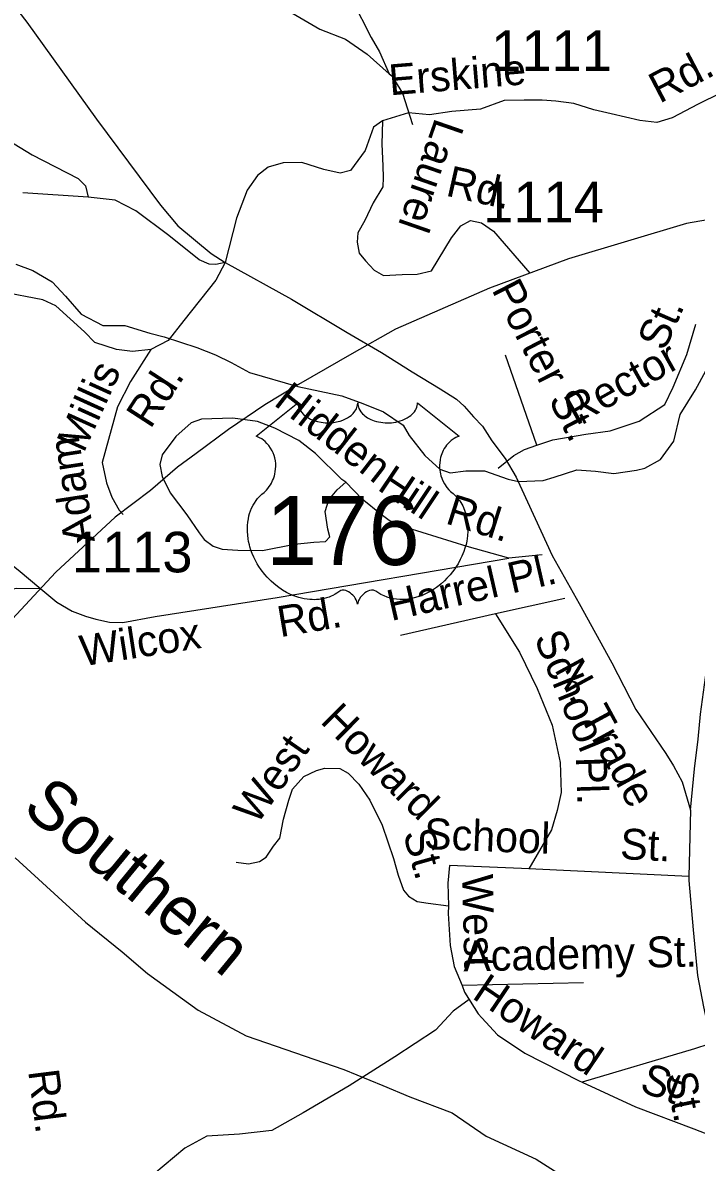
# Model space of a CAD drawing. Extents: x 990631 to 1056237, y 535999 to 585651.
# Drawn here: x 1029934 to 1032009, y 547537 to 551047 of the extents above; entities that cross this region are included whole.
import ezdxf

# ---------------------------------------------------------------- set-up
doc = ezdxf.new("R2010")
doc.units = 0
for name, color, linetype in [('Exist Boundary Political City Limit New', 7, 'Continuous'), ('Exist Hydrographic Creek Single Shore', 7, 'Continuous'), ('Exist Railroad Mainline', 7, 'Continuous'), ('Exist Railroad Mainline Label', 7, 'Continuous'), ('Exist Road Non-System Type 51', 7, 'Continuous'), ('Exist Road Non-System Type 51 Label', 7, 'Continuous'), ('Exist Road Primary NC Attributed', 7, 'Continuous'), ('Exist Road Primary US Attributed', 7, 'Continuous'), ('Exist Road Primary US Label', 7, 'Continuous'), ('Exist Road Primary US Shield CELL', 7, 'Continuous'), ('Exist Road Primary US Shield Number Label', 7, 'Continuous'), ('Exist Road Secondary Type 41 Attributed', 7, 'Continuous'), ('Exist Road Secondary Type 51 Attributed', 7, 'Continuous'), ('Exist Road Secondary Type 51 Label', 7, 'Continuous'), ('Exist Road Secondary Type 51 Number Label', 7, 'Continuous')]:
    doc.layers.add(name, color=color, linetype=linetype)

msp = doc.modelspace()

# ---------------------------------------------------------------- linework, layer by layer
at = {"layer": 'Exist Boundary Political City Limit New'}
msp.add_lwpolyline([(1032315.2, 550487.8), (1031979.1, 550428.5), (1031615.4, 550320.1), (1031372.3, 550229.8), (1031082.1, 550103), (1030947.7, 550027.3), (1030783.1, 549933), (1030679.9, 549869.8), (1030567.6, 549794.2), (1030468.1, 549720.6), (1030410.1, 549678.4), (1030326.8, 549606.4), (1030218.9, 549524.4), (1030035.4, 549354.2), (1029900.6, 549210.2)], dxfattribs=at)
at = {"layer": 'Exist Hydrographic Creek Single Shore'}
msp.add_lwpolyline([(1029912.2, 550304), (1029964.4, 550284.3), (1030024.7, 550248.8), (1030065, 550205.1), (1030113.4, 550149.4), (1030180.7, 550114.6), (1030248.1, 550114.6), (1030325.2, 550091.5), (1030369.5, 550079.9), (1030469.7, 550047.1), (1030527.4, 550024), (1030575.6, 550000.9), (1030632.8, 549969.5), (1030781.1, 549926.7), (1030917.4, 549897.8), (1030981.6, 549874.3), (1031045.8, 549848.8), (1031106, 549807.2), (1031124.3, 549775.3), (1031172.8, 549713.7), (1031219.1, 549672), (1031251.1, 549660.3), (1031299.1, 549666.6), (1031357.1, 549667.1), (1031429.3, 549641.7), (1031461.4, 549633.9), (1031537.4, 549636.6), (1031571.3, 549646.9), (1031641.1, 549669.5), (1031699.1, 549665.9), (1031755.1, 549658.4), (1031825.1, 549669), (1031851, 549675.2), (1031898.9, 549701.7), (1031940.4, 549758.1), (1031959.8, 549840.4), (1032007.2, 549916.9), (1032038.8, 549975.2)], dxfattribs=at)
at = {"layer": 'Exist Railroad Mainline'}
msp.add_lwpolyline([(1029909.8, 548474.7), (1030127.3, 548276.1), (1030240.3, 548184.7), (1030318.2, 548118.3), (1030473.9, 548005.6), (1030622, 547926.3), (1030922.7, 547822.4), (1031043.7, 547773.1), (1031126.6, 547738.4), (1031257.1, 547688.6), (1031361.6, 547617.5), (1031516.3, 547546.4), (1031606.1, 547489)], dxfattribs=at)
at = {"layer": 'Exist Road Non-System Type 51'}
for p, q in [((1031534.2, 549408.1), (1031431.7, 549397.3)), ((1031603.9, 549273.8), (1031390.3, 549226.7)), ((1031390.3, 549226.7), (1031097.8, 549159.9)), ((1031986.6, 548417), (1031493.1, 548440.7)), ((1031661.9, 548089.2), (1031287.4, 548081.1))]:
    msp.add_line(p, q, dxfattribs=at)
for points in [[(1030250.8, 551514.7), (1030343.7, 551477.6), (1030413.1, 551459.4), (1030458.6, 551444.1), (1030478.1, 551427.3), (1030518.2, 551364), (1030560.1, 551296.6), (1030611.7, 551224.9), (1030667.4, 551151.1), (1030737.7, 551092.7), (1030849.6, 551027.2), (1030928.6, 550996.6), (1030995.3, 550950.5), (1031063.3, 550890.3)], [(1030868.5, 551370.8), (1030876.1, 551292.6), (1030886.6, 551248.2), (1030914.4, 551175.2), (1030948.6, 551118.1), (1031006.9, 551002.1), (1031033.4, 550957.3), (1031063.3, 550890.3)], [(1029392.8, 550911.5), (1029486.1, 550886.4), (1029576.9, 550844.5), (1029699.3, 550793.9), (1029850.3, 550708.5), (1029962.7, 550640.8), (1030104.1, 550567.1), (1030127, 550545.3), (1030135.5, 550510.3)], [(1031063.3, 550890.3), (1031071.2, 550883.9), (1031103.5, 550830.8), (1031134.4, 550733.8)], [(1031517.8, 549745.7), (1031566.9, 549762.8), (1031669.2, 549779.8), (1031743.9, 549790.5), (1031833.5, 549820.4), (1031912.4, 549871.6), (1031938, 549924.9), (1031980.6, 550025.2), (1032008.3, 550119.1)], [(1031517.8, 549745.7), (1031421.8, 550023.1)], [(1030928.9, 549631.7), (1030917.1, 549640.2), (1030835.7, 549720.8), (1030784.8, 549760.5), (1030710.2, 549798.8), (1030656.8, 549818.5), (1030580.9, 549829), (1030484.9, 549826.1), (1030452.4, 549815), (1030405.1, 549772.5), (1030363.2, 549715.9), (1030356.2, 549686.1), (1030363.1, 549649.7), (1030387.4, 549599), (1030439.3, 549531.3), (1030477.6, 549476.2), (1030493, 549455.4), (1030520.2, 549434.7), (1030548, 549425.7), (1030596, 549422.2), (1030672, 549421.8), (1030770.6, 549440.6), (1030830.9, 549446.6), (1030867, 549449.5), (1030879.5, 549463.1), (1030874.2, 549487.4), (1030865.8, 549541.6), (1030877.2, 549577.3), (1030902.2, 549608.5), (1030928.9, 549631.7)], [(1031398.5, 549675), (1031447.4, 549713.7), (1031479.4, 549732.9), (1031517.8, 549745.7)], [(1031431.7, 549397.3), (1031302.8, 549433.5), (1031118.5, 549491.5), (1031063.1, 549513.4), (1031037.7, 549532.1), (1030979.3, 549580.1), (1030928.9, 549631.7)], [(1029800.8, 549467.8), (1029816.1, 549443.3), (1029919.5, 549361.9), (1029989.8, 549303.5)], [(1029989.8, 549303.5), (1030038.5, 549261.9), (1030085.6, 549234.4), (1030127.1, 549219.1), (1030158.9, 549210.1), (1030200.6, 549200.6), (1030242.5, 549199.4), (1030341.2, 549218.2), (1030717.3, 549276.3), (1031431.7, 549397.3)], [(1029989.8, 549303.5), (1029913.7, 549304), (1029869.3, 549293.3), (1029828.8, 549276.7), (1029800.1, 549253.5), (1029775.1, 549224.4), (1029767.5, 549174.5), (1029755, 549099)], [(1031390.3, 549226.7), (1031464.5, 549108.1), (1031518.9, 548996.4), (1031565.2, 548882.8), (1031589.7, 548767.9), (1031592.7, 548675.8), (1031580.9, 548620), (1031562.9, 548560.6), (1031493.1, 548440.7)], [(1030591.2, 548461.7), (1030628.9, 548456.5), (1030663.3, 548463.4), (1030683.7, 548476.8), (1030706.8, 548510), (1030725.5, 548535.4), (1030737.5, 548593.2), (1030753.3, 548652.7), (1030764.4, 548686.3), (1030799.8, 548725.2), (1030838.4, 548744), (1030864.5, 548751.1), (1030910.5, 548749.8), (1030936, 548734.9), (1030969.2, 548701.8), (1031003.6, 548652.7), (1031041, 548575.3), (1031075.8, 548472.1), (1031090.2, 548421.6), (1031106.6, 548375.1), (1031122.1, 548356.6), (1031149.5, 548339.8), (1031183.4, 548334.7), (1031245.3, 548326.7)], [(1031493.1, 548440.7), (1031471.1, 548441.6), (1031249.2, 548450.6), (1031243.5, 548396.7), (1031245.3, 548326.7)], [(1031245.3, 548326.7), (1031244.4, 548302.7), (1031251.2, 548204.3), (1031263.1, 548140), (1031287.4, 548081.1)], [(1031287.4, 548081.1), (1031294.8, 548061), (1031336.6, 547993.5), (1031348.2, 547981.1)], [(1031309.5, 548038.3), (1031260.4, 548001.9), (1031205.1, 547943.5), (1031080.4, 547861.3), (1030939.4, 547772.2), (1030797.3, 547688.6), (1030701.1, 547634.2), (1030601.4, 547623.1), (1030500.5, 547617.5), (1030433.6, 547579.8), (1030337.5, 547500.4), (1030270.6, 547429.3), (1030230.6, 547371.3), (1030232, 547313.4), (1030235.4, 547293.3), (1030257, 547277.6), (1030290.7, 547268.5), (1030430.6, 547262.1)], [(1031348.2, 547981.1), (1031396.6, 547929.5), (1031480.8, 547872.8), (1031648.2, 547787.4), (1031658.1, 547783)], [(1032048, 547900.6), (1032003.7, 547886), (1031658.1, 547783)], [(1031658.1, 547783), (1031821.8, 547707.8), (1032001.7, 547640), (1032102.6, 547600.8)]]:
    msp.add_lwpolyline(points, dxfattribs=at)
at = {"layer": 'Exist Road Primary NC Attributed'}
msp.add_lwpolyline([(1031991.1, 548621), (1032003.3, 548748.6), (1032014.7, 548840), (1032022.6, 548916.7), (1032040.3, 549052.3), (1032067.8, 549166.3), (1032085.5, 549243), (1032107.1, 549315.7), (1032130.6, 549476.9), (1032099.2, 549712.8), (1032118.9, 549791.4), (1032152.2, 549895.6), (1032173.9, 549982), (1032177.8, 550080.3), (1032177.8, 550186.5), (1032197.4, 550247.4), (1032348.7, 550424.3), (1032370.2, 550499.1)], dxfattribs=at)
at = {"layer": 'Exist Road Primary US Attributed'}
for points in [[(1028663.1, 551794), (1028748.1, 551769.7), (1028821.5, 551746.1), (1028864.3, 551725.4), (1028921.1, 551689.7), (1028948.3, 551666.7), (1028972.5, 551645.6), (1029182.8, 551417.8), (1029236.5, 551379.7), (1029268.5, 551363.9), (1029300.5, 551351.9), (1029393, 551323.8), (1029503.5, 551296.6), (1029677.5, 551264.2), (1029741.6, 551243.4), (1029777.2, 551225.2), (1029810.4, 551201.7), (1029865, 551154.9), (1029945.8, 551049.7), (1030160.9, 550750.5), (1030358, 550485.6), (1030412, 550421.9), (1030514.5, 550336), (1030557.1, 550309.2)], [(1030557.1, 550309.2), (1030762.1, 550195.3), (1030932.9, 550093.2), (1031039, 550031.5), (1031134, 549971.8), (1031219.9, 549919.3), (1031270.4, 549887.9), (1031293.6, 549865.7), (1031322.9, 549833.3), (1031350.2, 549805), (1031379.5, 549759.5), (1031419.9, 549704.9), (1031454.3, 549647.3), (1031565.4, 549405.6), (1031648.3, 549258), (1031749.4, 549075), (1031823.1, 548931.4), (1031915.1, 548795.9), (1031939.3, 548757.5), (1031965.6, 548709), (1031991.1, 548621)], [(1031991.1, 548621), (1031986.6, 548417), (1031986.1, 548405), (1031999.3, 548252.5), (1032012.8, 548111.9), (1032031.3, 548015.4), (1032054.5, 547911.3), (1032078.8, 547819.2), (1032103, 547685.8), (1032131.3, 547551.3), (1032182.8, 547297.5), (1032199, 547219.7), (1032210.1, 547179.2), (1032231.3, 547137.8), (1032259.6, 547102.4), (1032311.2, 547066), (1032444.6, 546970.9), (1032553.7, 546906.2), (1032630.5, 546861.7), (1032739.1, 546782.3), (1032803.9, 546737.7), (1032850.5, 546702.3), (1032897.1, 546653.6)]]:
    msp.add_lwpolyline(points, dxfattribs=at)
at = {"layer": 'Exist Road Primary US Shield CELL'}
msp.add_lwpolyline([(1030781.8, 549876.1), (1030782.1, 549870.8), (1030783.4, 549864.5), (1030784.4, 549861.2), (1030787.3, 549855), (1030792.2, 549847.6), (1030799, 549840.4), (1030806.7, 549834.1), (1030811.8, 549830.7), (1030820.6, 549826), (1030830.5, 549821.8), (1030841.6, 549818.6), (1030852.9, 549816.4), (1030865.3, 549815), (1030877.6, 549814.8), (1030890.8, 549815.7), (1030905.3, 549818.6), (1030912.1, 549820.3), (1030919.6, 549822.9), (1030926.6, 549825.8), (1030934.3, 549829.9), (1030940.4, 549833.8), (1030945.3, 549837.3), (1030952.1, 549843.9), (1030957.5, 549850.6), (1030959.8, 549854.4), (1030961.8, 549858.1), (1030964.5, 549865.8), (1030965.2, 549869.2), (1030965.8, 549876.4), (1030966.2, 549870.4), (1030966.8, 549866.7), (1030967.8, 549863), (1030969.3, 549859.1), (1030972.1, 549853.7), (1030975.1, 549849.1), (1030980.8, 549842.3), (1030984.4, 549839), (1030987.7, 549836.3), (1030996.4, 549830.3), (1031006.6, 549825.2), (1031011.6, 549823), (1031016.8, 549821.1), (1031023.3, 549819.2), (1031030.1, 549817.6), (1031036.8, 549816.4), (1031043.6, 549815.4), (1031050.6, 549814.9), (1031056.3, 549814.8), (1031063.3, 549814.8), (1031069.7, 549815.2), (1031076.3, 549816), (1031083.6, 549817.2), (1031089.5, 549818.5), (1031097.2, 549820.5), (1031104.2, 549823), (1031110.4, 549825.7), (1031118.3, 549829.9), (1031124.8, 549833.9), (1031129.5, 549837.7), (1031135.1, 549842.9), (1031140.4, 549849), (1031143.6, 549853.5), (1031145.8, 549858.1), (1031147.8, 549863), (1031149.1, 549868.2), (1031149.7, 549872.7), (1031149.8, 549876.5), (1031278.4, 549774), (1031275.4, 549772.9), (1031268.4, 549769.5), (1031262.8, 549766.2), (1031254, 549760), (1031250.2, 549756.5), (1031246.4, 549753), (1031242.9, 549749.2), (1031239.8, 549745.6), (1031236.1, 549740.4), (1031232.8, 549735.3), (1031229.5, 549729.6), (1031227.1, 549724.6), (1031223.2, 549714.3), (1031221.3, 549707.8), (1031220, 549702.2), (1031218.5, 549690.7), (1031218.1, 549685.3), (1031218.1, 549679.9), (1031218.4, 549674.2), (1031219, 549668.7), (1031220, 549663), (1031220.9, 549658), (1031222.5, 549651.8), (1031224.7, 549644.7), (1031227.6, 549637.8), (1031233.4, 549626.6), (1031241, 549615.2), (1031246.4, 549608.8), (1031251.7, 549603.4), (1031259.6, 549596.7), (1031263.9, 549592.9), (1031268.9, 549587.9), (1031276.9, 549578.6), (1031280.2, 549574.2), (1031283.5, 549569.2), (1031286.5, 549564.2), (1031289.6, 549558.7), (1031292, 549553.9), (1031296.5, 549542.9), (1031299.8, 549532.2), (1031301.3, 549526.5), (1031303.7, 549513.9), (1031304.6, 549507.7), (1031305.6, 549495.4), (1031305.7, 549480.5), (1031304.5, 549466.4), (1031301.9, 549449.9), (1031299.7, 549440), (1031296.3, 549428.5), (1031293, 549418.6), (1031287.1, 549403.9), (1031281.9, 549393.3), (1031275.2, 549380.8), (1031270.5, 549373.3), (1031265.1, 549365.2), (1031258.4, 549355.9), (1031250.5, 549346.1), (1031241, 549335.7), (1031233.3, 549328), (1031223.3, 549319), (1031217.2, 549314), (1031208.6, 549307.5), (1031196.7, 549299.6), (1031185, 549292.8), (1031175.1, 549287.7), (1031166.3, 549283.9), (1031154.9, 549279.6), (1031135.9, 549274.3), (1031129, 549272.9), (1031120.8, 549271.7), (1031113.1, 549270.9), (1031105.7, 549270.5), (1031095.6, 549270.5), (1031085.7, 549271.2), (1031076.3, 549272.6), (1031066.5, 549274.6), (1031056.2, 549277.7), (1031046.9, 549281.3), (1031037.5, 549286), (1031021.6, 549296), (1031017, 549298.4), (1031014.4, 549299.1), (1031008.3, 549299.4), (1031002.5, 549298.2), (1030996.6, 549295.8), (1030993, 549293.9), (1030988.2, 549290.8), (1030984.6, 549287.9), (1030980.2, 549283.8), (1030977.2, 549280.3), (1030974.8, 549277.5), (1030970.4, 549270.5), (1030968.8, 549267.1), (1030967.1, 549262.8), (1030965.6, 549256.4), (1030963.6, 549264.5), (1030961.2, 549269.8), (1030958.5, 549274.3), (1030955.7, 549278.4), (1030951.2, 549283.5), (1030947.2, 549287.4), (1030942.3, 549291.4), (1030937.1, 549294.5), (1030933, 549296.6), (1030929.2, 549298), (1030924.6, 549299.2), (1030920.8, 549299.5), (1030917.7, 549299.4), (1030913.4, 549298.4), (1030907.6, 549294.2), (1030902, 549290.4), (1030896, 549286.7), (1030888.9, 549282.9), (1030883.7, 549280.5), (1030877.4, 549278.1), (1030870.1, 549275.6), (1030862.2, 549273.6), (1030854.1, 549272), (1030847, 549270.8), (1030839.3, 549270.2), (1030832.4, 549269.9), (1030825.2, 549270), (1030818.4, 549270.5), (1030810.6, 549271.2), (1030800.9, 549272.7), (1030792.8, 549274.5), (1030784.3, 549276.8), (1030775.6, 549279.5), (1030766.3, 549283.1), (1030754.6, 549288.2), (1030746.4, 549292.3), (1030733.6, 549299.7), (1030718.6, 549310.1), (1030707.2, 549319.3), (1030698.9, 549326.8), (1030686.7, 549339.3), (1030679.5, 549347.4), (1030668.2, 549362), (1030661, 549372.6), (1030656.3, 549380.3), (1030649.5, 549392.8), (1030645.7, 549400.6), (1030640.9, 549412), (1030637, 549422.4), (1030633.8, 549432.3), (1030632.1, 549438.6), (1030629.7, 549449.6), (1030628.2, 549457.5), (1030626.8, 549468.2), (1030626, 549479.5), (1030625.8, 549489.9), (1030626.1, 549498.6), (1030627.1, 549508.7), (1030628.8, 549519.4), (1030630.8, 549528.6), (1030632.7, 549535.2), (1030635.4, 549543.3), (1030639, 549552.1), (1030643.3, 549560.7), (1030647.4, 549567.7), (1030652.5, 549575.3), (1030657.5, 549581.8), (1030664, 549588.9), (1030670.9, 549595.5), (1030677.1, 549600.5), (1030684.6, 549607.8), (1030688.5, 549612.2), (1030693.1, 549618.4), (1030696.8, 549624.1), (1030699.8, 549629.2), (1030703.7, 549636.7), (1030706.1, 549642.3), (1030709, 549651), (1030710.5, 549657.1), (1030712, 549664.9), (1030713, 549672.3), (1030713.4, 549681.5), (1030713.2, 549689.1), (1030712.2, 549698), (1030710.5, 549706.5), (1030708.5, 549713.9), (1030705.3, 549722.4), (1030702.4, 549728.7), (1030697.5, 549737.1), (1030692, 549744.9), (1030686.3, 549751.3), (1030680.6, 549757), (1030675.2, 549761.3), (1030670, 549765), (1030663.4, 549768.9), (1030657.1, 549772.1), (1030653.2, 549773.6)], close=True, dxfattribs=at)
at = {"layer": 'Exist Road Secondary Type 41 Attributed'}
msp.add_lwpolyline([(1030328.8, 550041.2), (1030266, 549941.8), (1030225.2, 549864.5), (1030178.6, 549692.5), (1030191.7, 549629.8), (1030207.7, 549586.1), (1030231, 549545.2), (1030242.7, 549532.1)], dxfattribs=at)
at = {"layer": 'Exist Road Secondary Type 51 Attributed'}
for points in [[(1032421.7, 550791.1), (1032290, 550814.6), (1032195.9, 550840.5), (1032141.8, 550845.2), (1032084, 550830.8), (1032015.3, 550796.4), (1031935.1, 550754), (1031888.2, 550740.2), (1031835.5, 550746), (1031747.3, 550766.6), (1031693.5, 550779.2), (1031631.6, 550798.7), (1031576.6, 550805.6), (1031534.2, 550809), (1031479.3, 550809), (1031417.4, 550807.8), (1031344, 550781.2), (1031255.6, 550774), (1031187.2, 550763.2), (1031121.9, 550770), (1031041.8, 550744.8)], [(1031041.8, 550744.8), (1031014.3, 550725.3), (1030989.1, 550654.3), (1030943.3, 550592.4), (1030911.8, 550584), (1030861.9, 550595.1), (1030794.1, 550617.2), (1030735.9, 550615.8), (1030690.3, 550602), (1030657, 550577.1), (1030625.2, 550531.4), (1030592, 550445.5), (1030557.1, 550309.2)], [(1031041.8, 550744.8), (1031040.6, 550673.8), (1031042.9, 550606.1), (1031044, 550570.6), (1031042.9, 550542), (1031013.1, 550492.7), (1030987.9, 550437.7), (1030966.2, 550399.9), (1030963.9, 550371.2), (1030970.7, 550338), (1030990.2, 550313.9), (1031016.6, 550285.3), (1031045.2, 550269.2), (1031102.5, 550271.5), (1031149.4, 550272.7), (1031192.9, 550283), (1031254.8, 550385), (1031283.4, 550421.6), (1031313.2, 550437.7), (1031347.6, 550430.8), (1031384.2, 550405.6), (1031496.2, 550275.9)], [(1030557.1, 550309.2), (1030528.7, 550302.5), (1030508.5, 550303.5), (1030477.2, 550316.6), (1030384.2, 550392.4), (1030282.2, 550468.3), (1030218.5, 550500.6), (1030135.5, 550510.3), (1029933.5, 550522.9)], [(1030557.1, 550309.2), (1030528.3, 550254.3), (1030430, 550129.7), (1030381.6, 550068.7), (1030328.8, 550041.2)], [(1030328.8, 550041.2), (1030272.2, 550034.1), (1030222.4, 550041), (1030156, 550061.8), (1030123.4, 550095.6), (1030035.2, 550175.4), (1029995.3, 550193.6), (1029866.7, 550218.6)]]:
    msp.add_lwpolyline(points, dxfattribs=at)

# ---------------------------------------------------------------- texts
at = {"layer": 'Exist Railroad Mainline Label'}
msp.add_text('Southern', height=150, rotation=320.5949, dxfattribs=at).set_placement((1029927.9, 548619.7))
at = {"layer": 'Exist Road Non-System Type 51 Label'}
for s, rotation, p in [('Porter St.', 297.3213, (1031377.2, 550225.3)), ('St.', 66.3231, (1031911.7, 550032.7)), ('Rector', 29.3875, (1031639.1, 549805)), ('Hidden', 322.0459, (1030703.7, 549872)), ('Hill', 326.2631, (1031023, 549610.6)), ('Rd.', 342.5498, (1031232.8, 549505.9)), ('Harrel Pl.', 12.855, (1031068.7, 549203.8)), ('Rd.', 9.6167, (1030726.9, 549154.1)), ('Wilcox ', 8.7742, (1030117.7, 549064.4)), ('School', 292.1909, (1031508.2, 549152.8)), ('Howard', 315.0561, (1030847.4, 548892.8)), ('West', 55.1565, (1030654.6, 548572.8)), ('Pl.', 271.8318, (1031638.4, 548785.1)), ('School', 357.6591, (1031169, 548502.4)), ('St.', 285.8998, (1031104.7, 548550.1)), ('St.', 357.2453, (1031773.2, 548470.9)), ('West', 271.4626, (1031287.3, 548423)), ('Academy St.', 1.2336, (1031291.9, 548124.3)), ('Howard', 326.0628, (1031314.8, 548043.8)), ('Rd.', 277.2307, (1029950.1, 547817.7)), ('St.', 339.3362, (1031830.8, 547757.1))]:
    msp.add_text(s, height=95, rotation=rotation, dxfattribs=at).set_placement(p)
at = {"layer": 'Exist Road Primary US Label'}
for s, rotation, p in [('N. Trade', 298.4661, (1031570.5, 549055.4)), ('St.', 281.5318, (1031912.7, 547806.2))]:
    msp.add_text(s, height=95, rotation=rotation, dxfattribs=at).set_placement(p)
at = {"layer": 'Exist Road Primary US Shield Number Label'}
msp.add_text('176', height=212.5, dxfattribs=at).set_placement((1030682.9, 549376.8))
at = {"layer": 'Exist Road Secondary Type 51 Label'}
for s, rotation, p in [('Erskine', 4.6728, (1031065.5, 550823.7)), ('Rd.', 27.5068, (1031896.1, 550797.4)), ('Laurel', 250.8417, (1031205.4, 550757.7)), ('Rd.', 347.2739, (1031234.2, 550515.3)), ('Millis', 65.6305, (1030121.5, 549719.3)), ('Rd.', 57.0416, (1030326.9, 549793.4)), ('Adam', 98.7737, (1030156.1, 549449.9))]:
    msp.add_text(s, height=95, rotation=rotation, dxfattribs=at).set_placement(p)
at = {"layer": 'Exist Road Secondary Type 51 Number Label'}
for s, p in [('1111', (1031377.5, 550899)), ('1114', (1031352.8, 550432.6)), ('1113', (1030084.9, 549354.1))]:
    msp.add_text(s, height=125, dxfattribs=at).set_placement(p)

doc.saveas('drawing.dxf')
